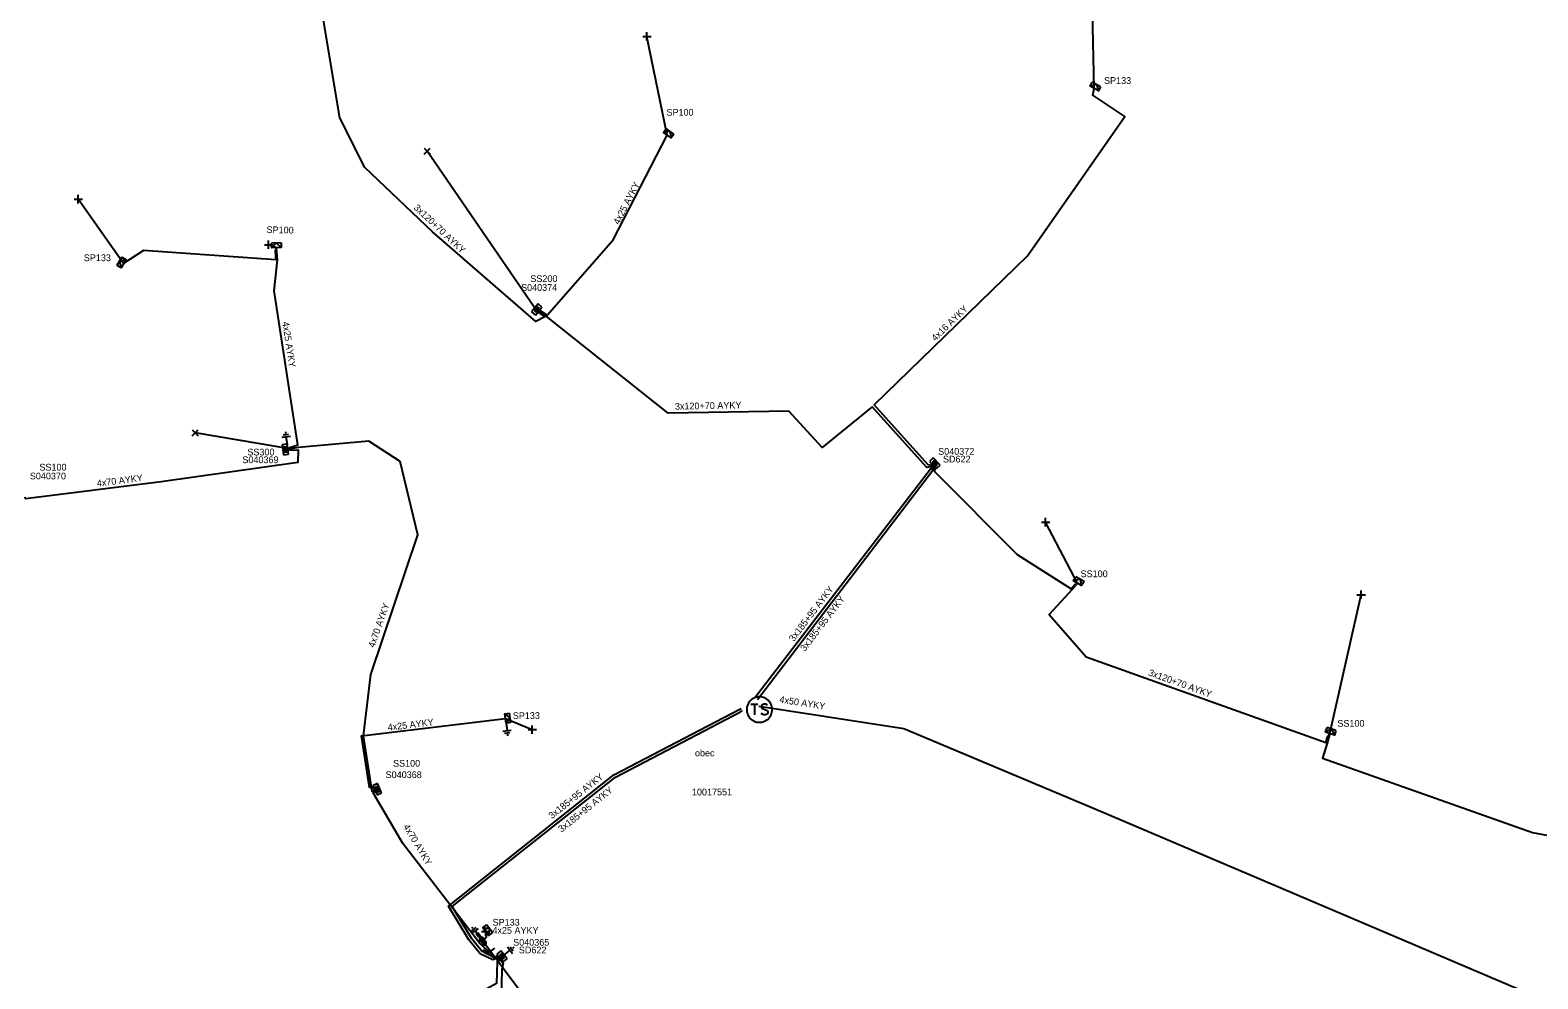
# Model space of a CAD drawing. Extents: x -748492 to -735633, y -1146251 to -1139940.
# Drawn here: x -740893.8 to -740670.5, y -1144381.6 to -1144241 of the extents above; entities that cross this region are included whole.
import ezdxf

# ---------------------------------------------------------------- set-up
doc = ezdxf.new("R2010")
doc.units = 0
for name, color, linetype in [('Vrstva 1', 7, 'Continuous'), ('Vrstva 13', 7, 'Continuous'), ('Vrstva 14', 7, 'Continuous'), ('Vrstva 15', 7, 'Continuous'), ('Vrstva 16', 7, 'Continuous'), ('Vrstva 18', 7, 'Continuous'), ('Vrstva 2', 7, 'Continuous'), ('Vrstva 25', 7, 'Continuous'), ('Vrstva 26', 7, 'Continuous'), ('Vrstva 27', 7, 'Continuous'), ('Vrstva 28', 7, 'Continuous'), ('Vrstva 29', 7, 'Continuous'), ('Vrstva 30', 7, 'Continuous'), ('Vrstva 31', 7, 'Continuous'), ('Vrstva 33', 7, 'Continuous'), ('Vrstva 34', 7, 'Continuous'), ('Vrstva 5', 7, 'Continuous'), ('Vrstva 52', 7, 'Continuous'), ('Vrstva 54', 7, 'Continuous'), ('Vrstva 59', 7, 'Continuous'), ('Vrstva 6', 7, 'Continuous'), ('Vrstva 8', 7, 'Continuous'), ('Vrstva 9', 7, 'Continuous')]:
    doc.layers.add(name, color=color, linetype=linetype)

# ---------------------------------------------------------------- blocks, each defined once
blk = doc.blocks.new('NN450')
at = {"layer": 'Vrstva 2'}
for points in [[(0, 0), (0, 0.07), (-0.01, 0.13), (-0.03, 0.19), (-0.05, 0.25), (-0.08, 0.31), (-0.12, 0.37), (-0.16, 0.42), (-0.21, 0.46), (-0.26, 0.51), (-0.31, 0.54), (-0.37, 0.57), (-0.43, 0.59), (-0.5, 0.61), (-0.56, 0.62), (-0.63, 0.62), (-0.69, 0.62), (-0.75, 0.61), (-0.82, 0.59), (-0.88, 0.57), (-0.94, 0.54), (-0.99, 0.51), (-1.04, 0.46), (-1.09, 0.42), (-1.13, 0.37), (-1.17, 0.31), (-1.2, 0.25), (-1.22, 0.19), (-1.24, 0.13), (-1.25, 0.07), (-1.25, 0), (-1.25, -0.07), (-1.24, -0.13), (-1.22, -0.19), (-1.2, -0.25), (-1.17, -0.31), (-1.13, -0.37), (-1.09, -0.42), (-1.04, -0.46), (-0.99, -0.51), (-0.94, -0.54), (-0.88, -0.57), (-0.82, -0.59), (-0.75, -0.61), (-0.69, -0.62), (-0.62, -0.63), (-0.56, -0.62), (-0.5, -0.61), (-0.43, -0.59), (-0.37, -0.57), (-0.31, -0.54), (-0.26, -0.51), (-0.21, -0.46), (-0.16, -0.42), (-0.12, -0.37), (-0.08, -0.31), (-0.05, -0.25), (-0.03, -0.19), (-0.01, -0.13), (0, -0.07), (0, 0)], [(1.25, 0), (1.25, 0.07), (1.24, 0.13), (1.22, 0.19), (1.2, 0.25), (1.17, 0.31), (1.13, 0.37), (1.09, 0.42), (1.04, 0.46), (0.99, 0.51), (0.94, 0.54), (0.88, 0.57), (0.82, 0.59), (0.75, 0.61), (0.69, 0.62), (0.62, 0.62), (0.56, 0.62), (0.5, 0.61), (0.43, 0.59), (0.37, 0.57), (0.31, 0.54), (0.26, 0.51), (0.21, 0.46), (0.16, 0.42), (0.12, 0.37), (0.08, 0.31), (0.05, 0.25), (0.03, 0.19), (0.01, 0.13), (0, 0.07), (0, 0), (0, -0.07), (0.01, -0.13), (0.03, -0.19), (0.05, -0.25), (0.08, -0.31), (0.12, -0.37), (0.16, -0.42), (0.21, -0.46), (0.26, -0.51), (0.31, -0.54), (0.37, -0.57), (0.43, -0.59), (0.5, -0.61), (0.56, -0.62), (0.63, -0.63), (0.69, -0.62), (0.75, -0.61), (0.82, -0.59), (0.88, -0.57), (0.94, -0.54), (0.99, -0.51), (1.04, -0.46), (1.09, -0.42), (1.13, -0.37), (1.17, -0.31), (1.2, -0.25), (1.22, -0.19), (1.24, -0.13), (1.25, -0.07), (1.25, 0)], [(-1.25, 0), (1.25, 0)], [(-1.23, -0.16), (-0.02, -0.16)], [(-1.16, -0.32), (-0.09, -0.32)], [(-1.03, -0.47), (-0.22, -0.47)], [(0.02, -0.16), (1.23, -0.16)], [(0.09, -0.32), (1.16, -0.32)], [(0.22, -0.47), (1.03, -0.47)]]:
    blk.add_lwpolyline(points, dxfattribs=at)
blk = doc.blocks.new('NN840')
at = {"layer": 'Vrstva 15'}
for points in [[(0, 0.62), (0, -0.63)], [(-0.75, -0.71), (-0.75, -0.66)], [(-0.73, -0.76), (-0.75, -0.71)], [(-0.66, -0.8), (-0.73, -0.76)], [(-0.63, -0.8), (-0.66, -0.8)], [(-0.56, -0.76), (-0.63, -0.8)], [(-0.54, -0.71), (-0.56, -0.76)], [(-0.54, -0.38), (-0.54, -0.71)], [(-0.33, -0.38), (-0.33, -0.8)], [(-0.33, -0.64), (-0.13, -0.38)], [(-0.26, -0.56), (-0.09, -0.8)]]:
    blk.add_lwpolyline(points, dxfattribs=at)
blk = doc.blocks.new('NN800')
at = {"layer": 'Vrstva 1'}
for points in [[(-0.44, 0.44), (0.44, -0.44)], [(-0.44, -0.44), (0.44, 0.44)]]:
    blk.add_lwpolyline(points, dxfattribs=at)
blk = doc.blocks.new('NN820')
at = {"layer": 'Vrstva 13'}
for points in [[(0, 0), (0, -1.05)], [(-0.16, -0.81), (0.16, -0.81)], [(-0.16, -1.47), (-0.16, -0.81)], [(0.16, -1.47), (-0.16, -1.47)], [(0, -1.05), (-0.06, -0.93)], [(0, -1.05), (0.06, -0.93)], [(0, -1.47), (0, -1.87)], [(0.16, -0.81), (0.16, -1.47)]]:
    blk.add_lwpolyline(points, dxfattribs=at)
blk = doc.blocks.new('NN620')
at = {"layer": 'Vrstva 8'}
for points in [[(0.75, 0), (-0.75, 0)], [(-0.75, 0), (-0.75, -0.75)], [(0.75, -0.75), (0.75, 0)], [(-0.75, -0.75), (0.75, -0.75)], [(0.37, -0.18), (-0.38, -0.18)], [(-0.38, -0.18), (-0.38, -0.56)], [(-0.38, -0.56), (0.37, -0.56)], [(0.32, -0.23), (-0.33, -0.23)], [(-0.33, -0.23), (-0.33, -0.51)], [(-0.33, -0.51), (0.32, -0.51)], [(0.27, -0.27), (-0.28, -0.27)], [(-0.28, -0.27), (-0.28, -0.46)], [(-0.28, -0.46), (0.27, -0.46)], [(0.23, -0.32), (-0.23, -0.32)], [(-0.23, -0.32), (-0.23, -0.42)], [(-0.23, -0.42), (0.23, -0.42)], [(-0.19, -0.37), (0.19, -0.37)], [(0.23, -0.42), (0.23, -0.32)], [(0.27, -0.46), (0.27, -0.27)], [(0.32, -0.51), (0.32, -0.23)], [(0.37, -0.56), (0.37, -0.18)]]:
    blk.add_lwpolyline(points, dxfattribs=at)
blk = doc.blocks.new('NN630')
at = {"layer": 'Vrstva 9'}
for points in [[(0, -0.7), (-0.7, 0)], [(-0.7, -0.7), (-0.7, 0), (0.7, 0), (0.7, -0.7)], [(-0.7, -0.7), (0.7, -0.7)], [(0, -0.7), (0.7, 0)]]:
    blk.add_lwpolyline(points, dxfattribs=at)
blk = doc.blocks.new('NN810')
at = {"layer": 'Vrstva 14'}
for points in [[(0.63, -1.89), (-0.62, -1.89)], [(0.39, -2.2), (-0.4, -2.2)], [(0, -0.64), (0, -1.89)], [(0, -2.52), (-0.12, -2.52)], [(0.14, -2.52), (0, -2.52)]]:
    blk.add_lwpolyline(points, dxfattribs=at)
blk = doc.blocks.new('NN610')
at = {"layer": 'Vrstva 6'}
for points in [[(1.88, 0), (1.87, 0.2), (1.84, 0.39), (1.79, 0.58), (1.72, 0.77), (1.63, 0.94), (1.52, 1.11), (1.4, 1.26), (1.26, 1.4), (1.1, 1.53), (0.94, 1.63), (0.76, 1.72), (0.58, 1.8), (0.19, 1.88), (0.19, 1.88), (-0.01, 1.89), (-0.21, 1.88), (-0.4, 1.85), (-0.59, 1.8), (-0.78, 1.72), (-0.95, 1.63), (-1.12, 1.53), (-1.27, 1.4), (-1.41, 1.26), (-1.54, 1.11), (-1.64, 0.94), (-1.73, 0.77), (-1.8, 0.58), (-1.86, 0.39), (-1.89, 0.2), (-1.9, 0), (-1.89, -0.2), (-1.86, -0.39), (-1.8, -0.58), (-1.73, -0.77), (-1.64, -0.95), (-1.54, -1.11), (-1.41, -1.27), (-1.27, -1.41), (-1.12, -1.53), (-0.95, -1.64), (-0.78, -1.73), (-0.59, -1.8), (-0.4, -1.85), (-0.21, -1.88), (-0.01, -1.89), (0.19, -1.88), (0.39, -1.85), (0.58, -1.8), (0.76, -1.73), (0.94, -1.64), (1.1, -1.53), (1.26, -1.41), (1.4, -1.27), (1.52, -1.11), (1.63, -0.95), (1.72, -0.77), (1.79, -0.58), (1.84, -0.39), (1.87, -0.2), (1.88, 0)], [(-1.27, 0.78), (-0.26, 0.78)], [(-0.76, 0.78), (-0.76, -0.79)], [(1.19, 0.66), (0.94, 0.78), (0.62, 0.78), (0.37, 0.66), (0.24, 0.47), (0.24, 0.4), (0.37, 0.22), (1.12, -0.16), (1.25, -0.32), (1.25, -0.48), (1.12, -0.67), (0.87, -0.79), (0.62, -0.79), (0.49, -0.73), (0.24, -0.6)]]:
    blk.add_lwpolyline(points, dxfattribs=at)

msp = doc.modelspace()

# ---------------------------------------------------------------- linework, layer by layer
at = {"layer": 'Vrstva 1'}
msp.add_lwpolyline([(-740795.19, -1144419.42), (-740811.73, -1144396.08), (-740826.75, -1144375.97)], dxfattribs=at)
at = {"layer": 'Vrstva 5'}
for points in [[(-740818.49, -1144282.82), (-740817.58, -1144283.44), (-740818.92, -1144284.13), (-740834.2, -1144270.85), (-740844.25, -1144261.3), (-740847.95, -1144253.93), (-740851.05, -1144235.25), (-740855.75, -1144230.55), (-740856.09, -1144230.26)], [(-740855.51, -1144302.88), (-740854.15, -1144302.4), (-740857.66, -1144279.58), (-740857.2, -1144275.02), (-740857.34, -1144273.2), (-740857.51, -1144273.65), (-740857.4, -1144275.01), (-740877.04, -1144273.63), (-740880, -1144275.56)], [(-740760.06, -1144305.57), (-740760.99, -1144305.77), (-740769.07, -1144296.8), (-740776.48, -1144302.81), (-740781.44, -1144297.44), (-740799.28, -1144297.73), (-740817.38, -1144283.34), (-740818.36, -1144282.66)], [(-740842.86, -1144353.67), (-740843.16, -1144353.78), (-740844.44, -1144345.53), (-740843.34, -1144336.46), (-740836.41, -1144315.78), (-740839.02, -1144304.91), (-740843.63, -1144301.85), (-740854.09, -1144302.82), (-740855.49, -1144303.05)], [(-740855.48, -1144303.2), (-740854.11, -1144303.17), (-740854.19, -1144305.05), (-740874.39, -1144307.91), (-740894.51, -1144310.41), (-740894.57, -1144310.18)], [(-740786.39, -1144339.83), (-740760.43, -1144305.99), (-740759.96, -1144305.66)], [(-740786.08, -1144340.15), (-740760.09, -1144306.19), (-740759.87, -1144305.75)], [(-740759.78, -1144305.84), (-740759.83, -1144306.39), (-740747.59, -1144318.66), (-740739.6, -1144323.76), (-740739.06, -1144323.1), (-740738.65, -1144322.92), (-740739.43, -1144323.87), (-740742.86, -1144327.55), (-740737.35, -1144333.84), (-740701.86, -1144346.54), (-740701.58, -1144345.61), (-740701.25, -1144345.21), (-740701.67, -1144346.61), (-740702.35, -1144348.84), (-740671.24, -1144359.87), (-740667.31, -1144360.63), (-740659.25, -1144363.21), (-740657.67, -1144356.4), (-740657.61, -1144357.01), (-740659.05, -1144363.25), (-740640.37, -1144366.66), (-740640.43, -1144367.18)], [(-740824.46, -1144378.39), (-740825.26, -1144378.77), (-740827.17, -1144377.88), (-740828.83, -1144375.8), (-740831.85, -1144370.81), (-740807.34, -1144351.33), (-740788.77, -1144341.63), (-740788.48, -1144341.5)], [(-740824.57, -1144378.22), (-740825.14, -1144378.4), (-740826.92, -1144377.46), (-740828.38, -1144375.63), (-740831.31, -1144370.85), (-740807.12, -1144351.66), (-740788.58, -1144341.99), (-740788.31, -1144341.78)], [(-740824.32, -1144378.54), (-740824.6, -1144378.71), (-740827.2, -1144376.31), (-740838.59, -1144361.5), (-740843.02, -1144354.02), (-740842.76, -1144353.83)], [(-740824.18, -1144378.74), (-740824.61, -1144379.02), (-740824.74, -1144382.24), (-740833.53, -1144387.11), (-740845.69, -1144388.16), (-740851.46, -1144388.7), (-740851.95, -1144389.02), (-740852.61, -1144388.92), (-740859.98, -1144390.57), (-740879.54, -1144396), (-740879.59, -1144397.49), (-740879.78, -1144397.11), (-740879.74, -1144396.04), (-740899.66, -1144399.64), (-740917.82, -1144401.9), (-740923.45, -1144403.86), (-740923.55, -1144404.87)], [(-740824.07, -1144378.87), (-740823.74, -1144379.26), (-740823.94, -1144380.17), (-740823.99, -1144382.25), (-740823.97, -1144384.68), (-740823.18, -1144386.39), (-740820.82, -1144389.36), (-740818.12, -1144392.62), (-740814.63, -1144397.04), (-740812.09, -1144400.31), (-740808.81, -1144405.71), (-740805.74, -1144411.04), (-740804.52, -1144413.78), (-740802.38, -1144418.7), (-740802.01, -1144420.14), (-740802.09, -1144420.67), (-740801.54, -1144421.82), (-740801.32, -1144422.69), (-740799.8, -1144422.17)]]:
    msp.add_lwpolyline(points, dxfattribs=at)
at = {"layer": 'Vrstva 52'}
for points in [[(-740760.15, -1144305.47), (-740760.78, -1144305.4), (-740768.79, -1144296.51), (-740746.05, -1144274.41), (-740731.65, -1144253.74), (-740736.4, -1144250.57), (-740736.18, -1144249.61)], [(-740818.24, -1144282.51), (-740817.25, -1144283.19), (-740807.43, -1144272.05), (-740799.44, -1144256.52)], [(-740842.96, -1144353.36), (-740843.53, -1144353.21), (-740844.73, -1144345.56), (-740823.4, -1144342.97)], [(-740785.86, -1144341.14), (-740781.32, -1144341.84), (-740764.37, -1144344.48), (-740735.92, -1144356.43), (-740708.9, -1144367.92), (-740652.65, -1144391.9), (-740615.05, -1144407.9), (-740591.81, -1144421.76), (-740574.09, -1144435.81), (-740560.04, -1144448.3), (-740526.58, -1144480.28), (-740489.96, -1144515.15), (-740475.5, -1144528.84), (-740467.13, -1144533.92), (-740444.71, -1144539.3), (-739963.95, -1144656.12)], [(-740826.75, -1144375.97), (-740826.2, -1144375.29), (-740826.33, -1144374.56)]]:
    msp.add_lwpolyline(points, dxfattribs=at)
at = {"layer": 'Vrstva 59'}
for points in [[(-740736.18, -1144249.61), (-740736.63, -1144229)], [(-740799.44, -1144256.52), (-740802.44, -1144241.88)], [(-740819.14, -1144282.02), (-740835, -1144258.88)], [(-740880, -1144275.56), (-740886.69, -1144266)], [(-740857.34, -1144273.2), (-740858.5, -1144272.75)], [(-740856.55, -1144302.8), (-740869.38, -1144300.63)], [(-740738.65, -1144322.92), (-740743.38, -1144313.88)], [(-740701.25, -1144345.21), (-740696.63, -1144324.63)], [(-740823.4, -1144342.97), (-740819.44, -1144344.63)]]:
    msp.add_lwpolyline(points, dxfattribs=at)

# ---------------------------------------------------------------- block references
at = {"layer": 'Vrstva 13', "xscale": 0.5, "yscale": 0.5, "rotation": -53.12874164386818}
msp.add_blockref('NN450', (-740826.75, -1144375.97), dxfattribs=at)
at = {"layer": 'Vrstva 15'}
for p, rotation in [((-740855.63, -1144303.07), -172.11903618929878), ((-740823.4, -1144342.97), 6.91605281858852), ((-740826.75, -1144375.97), -143.12874158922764), ((-740824.21, -1144378.48), 128.54966946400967)]:
    msp.add_blockref('NN810', p, dxfattribs=dict(at, rotation=rotation))
at = {"layer": 'Vrstva 16', "rotation": -143.12874158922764}
msp.add_blockref('NN820', (-740826.75, -1144375.97), dxfattribs=at)
at = {"layer": 'Vrstva 18', "rotation": -53.12874172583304}
msp.add_blockref('NN840', (-740825.54, -1144377.41), dxfattribs=at)
at = {"layer": 'Vrstva 25'}
msp.add_blockref('NN610', (-740785.77, -1144341.65), dxfattribs=at)
at = {"layer": 'Vrstva 28'}
for p, rotation in [((-740818.47, -1144282.59), -128.93461947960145), ((-740855.63, -1144303.07), -82.11903605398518), ((-740760.06, -1144305.41), 134.17762791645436), ((-740842.74, -1144353.63), 114.608874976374), ((-740824.21, -1144378.48), 128.25854151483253)]:
    msp.add_blockref('NN620', p, dxfattribs=dict(at, rotation=rotation))
at = {"layer": 'Vrstva 31'}
for p, rotation in [((-740736.18, -1144249.61), 151.48402226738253), ((-740799.44, -1144256.52), 144.65378612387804), ((-740857.34, -1144273.2), -178.86182219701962), ((-740880, -1144275.56), -119.96091663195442), ((-740738.65, -1144322.92), 148.6429139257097), ((-740823.4, -1144342.97), 96.91605275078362), ((-740701.25, -1144345.21), 161.2181917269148), ((-740826.33, -1144374.56), 126.87125827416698)]:
    msp.add_blockref('NN630', p, dxfattribs=dict(at, rotation=rotation))
at = {"layer": 'Vrstva 34'}
for p, rotation in [((-740802.44, -1144241.88), 44.99999995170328), ((-740886.69, -1144266), 44.99999995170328), ((-740858.5, -1144272.75), 45), ((-740743.38, -1144313.88), 45), ((-740696.63, -1144324.63), 45), ((-740819.44, -1144344.63), 44.99999995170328), ((-740826.33, -1144374.56), 44.99999995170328)]:
    msp.add_blockref('NN800', p, dxfattribs=dict(at, rotation=rotation))
for p in [(-740835, -1144258.88), (-740869.38, -1144300.63)]:
    msp.add_blockref('NN800', p, dxfattribs=at)

# ---------------------------------------------------------------- texts
at = {"layer": 'Vrstva 26'}
msp.add_text('10017551', height=1, dxfattribs=at).set_placement((-740795.78, -1144354.38))
at = {"layer": 'Vrstva 27'}
msp.add_text('obec', height=1, dxfattribs=at).set_placement((-740795.33, -1144348.59))
at = {"layer": 'Vrstva 29'}
msp.add_text('S040374', height=1, rotation=0.104, dxfattribs=at).set_placement((-740821.09, -1144279.6))
for s, p in [('S040372', (-740759.3, -1144303.89)), ('S040369', (-740862.38, -1144305.13)), ('S040370', (-740893.87, -1144307.54)), ('S040368', (-740841.16, -1144351.81)), ('S040365', (-740822.27, -1144376.65))]:
    msp.add_text(s, height=1, dxfattribs=at).set_placement(p)
at = {"layer": 'Vrstva 30'}
msp.add_text('SS200', height=1, rotation=359.946, dxfattribs=at).set_placement((-740819.72, -1144278.29))
for s, p in [('SS300', (-740861.64, -1144303.99)), ('SS100', (-740892.45, -1144306.23)), ('SD622', (-740758.59, -1144305.03)), ('SS100', (-740840.06, -1144350.12)), ('SD622', (-740821.42, -1144377.79))]:
    msp.add_text(s, height=1, dxfattribs=at).set_placement(p)
at = {"layer": 'Vrstva 33'}
for s, rotation, p in [('SP133', 359.685, (-740734.73, -1144248.91)), ('SP100', 0.322, (-740799.55, -1144253.64)), ('SP100', 358.774, (-740858.81, -1144271.02)), ('SP133', 359.942, (-740885.87, -1144275.19))]:
    msp.add_text(s, height=1, rotation=rotation, dxfattribs=at).set_placement(p)
for s, p in [('SS100', (-740738.2, -1144322.03)), ('SP133', (-740822.32, -1144343.05)), ('SS100', (-740700.16, -1144344.2)), ('SP133', (-740825.31, -1144373.68))]:
    msp.add_text(s, height=1, dxfattribs=at).set_placement(p)
at = {"layer": 'Vrstva 54'}
for s, rotation, p in [('4x25 AYKY', 62.68, (-740806.6, -1144269.86)), ('4x16 AYKY', 44.194, (-740759.72, -1144287.13)), ('4x50 AYKY', 351.163, (-740782.87, -1144340.62)), ('4x25 AYKY', 6.921, (-740840.79, -1144344.8))]:
    msp.add_text(s, height=1, rotation=rotation, dxfattribs=at).set_placement(p)
msp.add_text('4x25 AYKY', height=1, dxfattribs=at).set_placement((-740825.34, -1144374.88))
at = {"layer": 'Vrstva 6'}
for s, rotation, p in [('3x120+70 AYKY', 316.859, (-740837.09, -1144267.38)), ('4x25 AYKY', 278.692, (-740856.48, -1144284.23)), ('3x120+70 AYKY', 1.11, (-740798.29, -1144297.21)), ('4x70 AYKY', 7.204, (-740883.88, -1144308.63)), ('3x185+95 AYKY', 52.53, (-740780.71, -1144331.66)), ('3x185+95 AYKY', 52.576, (-740779.04, -1144333.1)), ('4x70 AYKY', 70.756, (-740842.83, -1144332.55)), ('3x120+70 AYKY', 340.345, (-740728.26, -1144336.57)), ('3x185+95 AYKY', 38.485, (-740816.53, -1144357.92)), ('3x185+95 AYKY', 38.427, (-740815.11, -1144359.91)), ('4x70 AYKY', 300.963, (-740838.6, -1144358.99))]:
    msp.add_text(s, height=1, rotation=rotation, dxfattribs=at).set_placement(p)

doc.saveas('drawing.dxf')
